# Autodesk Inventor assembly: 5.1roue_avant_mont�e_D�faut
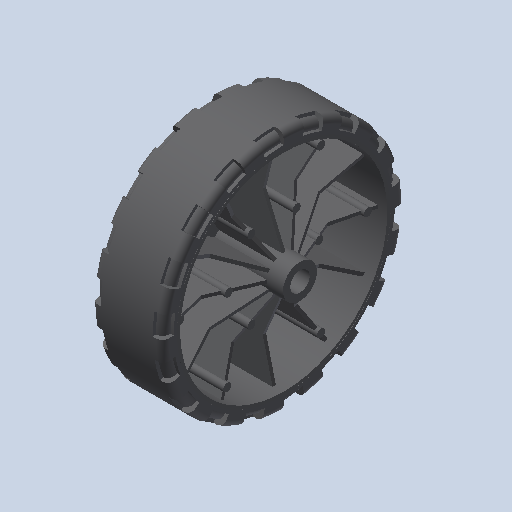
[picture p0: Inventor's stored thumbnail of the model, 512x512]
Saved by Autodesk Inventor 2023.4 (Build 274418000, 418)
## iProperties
Created: 2011-01
Part Number: 5.1roue_avant_mont�e_D�faut
Document SubType Name: Assembly
Designer: eric
Mass: 293.57 g
Surface Area: 1571.94 cm^2
Volume: 293.57 cm^3
Density: 1 g/cm^3
Author: eric
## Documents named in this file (3)
- C:\Users\bruno\Documents\1-Cours-2024-25\TSsI\7-Dynamique\chariot de golf\chariot_de_golf\chariot_de_golf_trolem\5.1roue_avant_montee_Defaut.iam
- C:\Users\bruno\Documents\1-Cours-2024-25\TSsI\7-Dynamique\chariot de golf\chariot_de_golf\chariot_de_golf_trolem\8pneu_Defaut.ipt
- C:\Users\bruno\Documents\1-Cours-2024-25\TSsI\7-Dynamique\chariot de golf\chariot_de_golf\chariot_de_golf_trolem\8.1jante_Defaut.ipt
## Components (2 placed, 2 different names)
1. 8pneu_Defaut:1
2. 8.1jante_Defaut:1
